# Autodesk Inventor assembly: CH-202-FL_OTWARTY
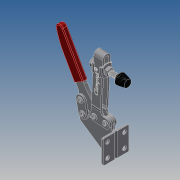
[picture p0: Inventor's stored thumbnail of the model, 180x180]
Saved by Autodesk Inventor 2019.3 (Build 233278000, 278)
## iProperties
Company: Î¢ÈíÖÐ¹ú
Created: 2011-05
Part Number: CH-202-FL_OTWARTY
Material: Ogólny
Description: STEP AP203
Document SubType Name: Assembly
Designer: CADENGINEERING4
Sending System: SolidWorks 2010
Preprocessor: SwSTEP 2.0
Title: CH-202-FL.STEP
Author: Î¢ÈíÓÃ»§
Revision Number: ÈÎºÎ
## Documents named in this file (9)
- E:\STRONA\Horizontal toggle clamp\CH-202-FL\CH-202-FL_OTWARTY.iam
- E:\STRONA\Horizontal toggle clamp\CH-202-FL\225-D-06.ipt
- E:\STRONA\Horizontal toggle clamp\CH-202-FL\56212-02.ipt
- E:\STRONA\Horizontal toggle clamp\CH-202-FL\FW516.ipt
- E:\STRONA\Horizontal toggle clamp\CH-202-FL\202-FL-02.ipt
- E:\STRONA\Horizontal toggle clamp\CH-202-FL\56212.ipt
- E:\STRONA\Horizontal toggle clamp\CH-202-FL\202-F-01.ipt
- E:\STRONA\Horizontal toggle clamp\CH-202-FL\203-F-04.ipt
- E:\STRONA\Horizontal toggle clamp\CH-202-FL\03.iam
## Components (14 placed, 14 different names)
1. 225-D-06_1 — Zestawiające:19, Zestawiające:20
2. 56212-02_2 — Równoległe:3, Zestawiające:2, Zestawiające:6
3. 225-D-06_3 — Zestawiające:23, Zestawiające:24, Zestawiające:26
4. FW516_4 — Równoległe:1, Równoległe:2, Zestawiające:1, Zestawiające:5, Zestawiające:6
5. 202-FL-02_5 — Równoległe:1, Zestawiające:5, Zestawiające:7, Zestawiające:9, Zestawiające:11, Zestawiające:12, Zestawiające:13, Zestawiające:23, Zestawiające:24, Zestawiające:25
6. 225-D-06_6 — Zestawiające:10, Zestawiające:12, Zestawiające:13
7. 225-D-06_7 — Zestawiające:21, Zestawiające:22, Zestawiające:27
8. FW516_8 — Równoległe:2, Zestawiające:3, Zestawiające:7, Zestawiające:8
9. 56212_9 — Równoległe:3, Zestawiające:1, Zestawiające:2, Zestawiające:3, Zestawiające:4, Zestawiające:9
10. 202-F-01_10 — Zestawiające:10, Zestawiające:11, Zestawiające:14, Zestawiające:15, Zestawiające:16, Zestawiające:17, Przejściowe:1
11. 203-F-04_11 — Zestawiające:14, Zestawiające:16, Zestawiające:18, Zestawiające:19, Zestawiające:20, Zestawiające:21, Zestawiające:22
12. 203-F-04_12 — Zestawiające:15, Zestawiające:17, Zestawiające:18
13. 03_13 [sub-assembly] — Zestawiające:25, Zestawiające:26, Zestawiające:27, Przejściowe:1
14. 56212-02_14 — Zestawiające:4, Zestawiające:8
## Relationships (31: Mate 27, Flush 3, Transitional 1)
- Równoległe:1 [Flush]: FW516_4 ↔ 202-FL-02_5
- Równoległe:2 [Flush]: FW516_4 ↔ FW516_8
- Równoległe:3 [Flush]: 56212-02_2 ↔ 56212_9
- Zestawiające:1 [Mate]: FW516_4 ↔ 56212_9
- Zestawiające:2 [Mate]: 56212-02_2 ↔ 56212_9
- Zestawiające:3 [Mate]: FW516_8 ↔ 56212_9
- Zestawiające:4 [Mate]: 56212_9 ↔ 56212-02_14
- Zestawiające:5 [Mate]: FW516_4 ↔ 202-FL-02_5
- Zestawiające:6 [Mate]: 56212-02_2 ↔ FW516_4
- Zestawiające:7 [Mate]: 202-FL-02_5 ↔ FW516_8
- Zestawiające:8 [Mate]: FW516_8 ↔ 56212-02_14
- Zestawiające:9 [Mate]: 202-FL-02_5 ↔ 56212_9
- Zestawiające:10 [Mate]: 225-D-06_6 ↔ 202-F-01_10
- Zestawiające:11 [Mate]: 202-FL-02_5 ↔ 202-F-01_10
- Zestawiające:12 [Mate]: 202-FL-02_5 ↔ 225-D-06_6
- Zestawiające:13 [Mate]: 202-FL-02_5 ↔ 225-D-06_6
- Zestawiające:14 [Mate]: 202-F-01_10 ↔ 203-F-04_11
- Zestawiające:15 [Mate]: 202-F-01_10 ↔ 203-F-04_12
- Zestawiające:16 [Mate]: 202-F-01_10 ↔ 203-F-04_11
- Zestawiające:17 [Mate]: 202-F-01_10 ↔ 203-F-04_12
- Zestawiające:18 [Mate]: 203-F-04_11 ↔ 203-F-04_12
- Zestawiające:19 [Mate]: 225-D-06_1 ↔ 203-F-04_11
- Zestawiające:20 [Mate]: 225-D-06_1 ↔ 203-F-04_11
- Zestawiające:21 [Mate]: 225-D-06_7 ↔ 203-F-04_11
- Zestawiające:22 [Mate]: 225-D-06_7 ↔ 203-F-04_11
- Zestawiające:23 [Mate]: 225-D-06_3 ↔ 202-FL-02_5
- Zestawiające:24 [Mate]: 225-D-06_3 ↔ 202-FL-02_5
- Zestawiające:25 [Mate]: 202-FL-02_5 ↔ 03_13
- Zestawiające:26 [Mate]: 225-D-06_3 ↔ 03_13
- Zestawiające:27 [Mate]: 225-D-06_7 ↔ 03_13
- Przejściowe:1 [Transitional]: 202-F-01_10 ↔ 03_13
